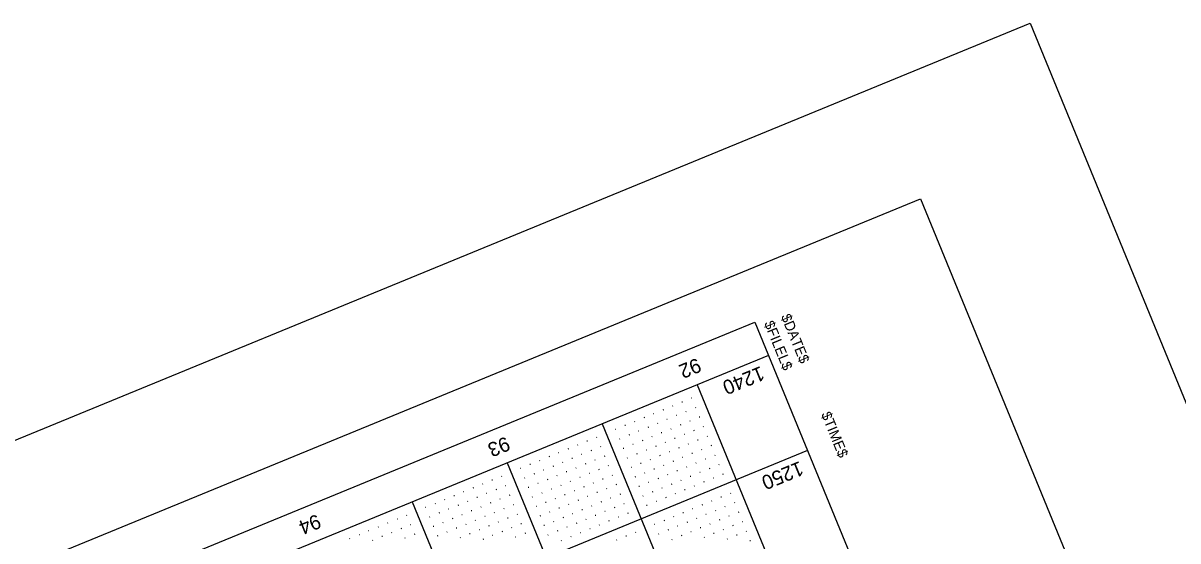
# Model space of a CAD drawing. Extents: x 2148770 to 2150891, y 142633 to 144465.
# Drawn here: x 2149944 to 2150507, y 144175 to 144427 of the extents above; entities that cross this region are included whole.
import ezdxf

# ---------------------------------------------------------------- set-up
doc = ezdxf.new("R2010")
doc.units = 0
for name, color, linetype in [('SHT_Plan_Profile_Sheet_Elev_Txt', 7, 'Continuous'), ('SHT_Plan_Profile_Sheet_Sta_Txt', 7, 'Continuous'), ('SHT_Plot_Shape_Full', 7, 'Continuous'), ('SHT_Plot_Shape_Half', 7, 'Continuous'), ('SHT_Plot_Stamp', 7, 'Continuous'), ('SHT_Profile_Grid_Major', 7, 'Continuous'), ('SHT_Profile_Grid_Minor', 7, 'Continuous'), ('SHT_Sheet_Border', 7, 'Continuous')]:
    doc.layers.add(name, color=color, linetype=linetype)

msp = doc.modelspace()

# ---------------------------------------------------------------- linework, layer by layer
at = {"layer": 'SHT_Plot_Shape_Full'}
msp.add_lwpolyline([(2150890.55, 143316.95), (2149225.42, 142633.31), (2148769.66, 143743.39), (2150434.78, 144427.04)], close=True, dxfattribs=at)
at = {"layer": 'SHT_Plot_Shape_Half'}
msp.add_lwpolyline([(2150799.14, 143324.02), (2149226.52, 142678.36), (2148808.74, 143695.93), (2150381.36, 144341.59)], close=True, dxfattribs=at)
at = {"layer": 'SHT_Profile_Grid_Major'}
for p, q in [((2150226.36, 144232.01), (2150416.26, 143769.48)), ((2150326.3, 144218.99), (2148869.31, 143620.81)), ((2150180.11, 144213.02), (2150370.01, 143750.49)), ((2150133.85, 144194.03), (2150323.76, 143731.5))]:
    msp.add_line(p, q, dxfattribs=at)
at = {"layer": 'SHT_Profile_Grid_Minor'}
for p, q in [((2150265.38, 144242.63), (2150265.15, 144242.53)), ((2150270, 144244.53), (2150269.77, 144244.43)), ((2150251.5, 144236.93), (2150251.27, 144236.83)), ((2150256.13, 144238.83), (2150255.9, 144238.73)), ((2150260.75, 144240.73), (2150260.52, 144240.63)), ((2150267.28, 144238), (2150267.05, 144237.91)), ((2150271.9, 144239.9), (2150271.67, 144239.81)), ((2150237.63, 144231.23), (2150237.4, 144231.14)), ((2150242.25, 144233.13), (2150242.02, 144233.04)), ((2150246.88, 144235.03), (2150246.65, 144234.94)), ((2150253.4, 144232.3), (2150253.17, 144232.21)), ((2150258.03, 144234.2), (2150257.8, 144234.11)), ((2150262.65, 144236.1), (2150262.42, 144236.01)), ((2150264.55, 144231.48), (2150264.32, 144231.38)), ((2150269.18, 144233.38), (2150268.95, 144233.28)), ((2150273.8, 144235.28), (2150273.57, 144235.18)), ((2150223.75, 144225.54), (2150223.52, 144225.44)), ((2150233, 144229.33), (2150232.77, 144229.24)), ((2150239.53, 144226.61), (2150239.29, 144226.51)), ((2150244.15, 144228.51), (2150243.92, 144228.41)), ((2150248.78, 144230.41), (2150248.55, 144230.31)), ((2150250.68, 144225.78), (2150250.44, 144225.69)), ((2150255.3, 144227.68), (2150255.07, 144227.58)), ((2150259.93, 144229.58), (2150259.7, 144229.48)), ((2150266.45, 144226.85), (2150266.22, 144226.76)), ((2150271.08, 144228.75), (2150270.84, 144228.66)), ((2150275.7, 144230.65), (2150275.47, 144230.55)), ((2150277.6, 144226.02), (2150277.37, 144225.93)), ((2150209.88, 144219.84), (2150209.64, 144219.74)), ((2150214.5, 144221.74), (2150214.27, 144221.64)), ((2150219.13, 144223.64), (2150218.89, 144223.54)), ((2150225.65, 144220.91), (2150225.42, 144220.82)), ((2150234.9, 144224.71), (2150234.67, 144224.61)), ((2150236.8, 144220.08), (2150236.57, 144219.99)), ((2150241.43, 144221.98), (2150241.19, 144221.89)), ((2150246.05, 144223.88), (2150245.82, 144223.79)), ((2150252.57, 144221.15), (2150252.34, 144221.06)), ((2150257.2, 144223.05), (2150256.97, 144222.96)), ((2150261.83, 144224.95), (2150261.59, 144224.86)), ((2150263.72, 144220.33), (2150263.49, 144220.23)), ((2150268.35, 144222.23), (2150268.12, 144222.13)), ((2150272.98, 144224.13), (2150272.74, 144224.03)), ((2150274.87, 144219.5), (2150274.64, 144219.41)), ((2150279.5, 144221.4), (2150279.27, 144221.3)), ((2150196, 144214.14), (2150195.77, 144214.05)), ((2150200.62, 144216.04), (2150200.39, 144215.95)), ((2150205.25, 144217.94), (2150205.02, 144217.84)), ((2150211.77, 144215.21), (2150211.54, 144215.12)), ((2150216.4, 144217.11), (2150216.17, 144217.02)), ((2150221.02, 144219.01), (2150220.79, 144218.92)), ((2150222.92, 144214.39), (2150222.69, 144214.29)), ((2150227.55, 144216.29), (2150227.32, 144216.19)), ((2150238.7, 144215.46), (2150238.47, 144215.36)), ((2150243.32, 144217.36), (2150243.09, 144217.26)), ((2150247.95, 144219.26), (2150247.72, 144219.16)), ((2150249.85, 144214.63), (2150249.62, 144214.54)), ((2150254.47, 144216.53), (2150254.24, 144216.43)), ((2150259.1, 144218.43), (2150258.87, 144218.33)), ((2150265.62, 144215.7), (2150265.39, 144215.61)), ((2150270.25, 144217.6), (2150270.02, 144217.51)), ((2150276.77, 144214.87), (2150276.54, 144214.78)), ((2150281.4, 144216.77), (2150281.17, 144216.68)), ((2150186.75, 144210.34), (2150186.52, 144210.25)), ((2150191.37, 144212.24), (2150191.14, 144212.15)), ((2150197.9, 144209.52), (2150197.67, 144209.42)), ((2150202.52, 144211.42), (2150202.29, 144211.32)), ((2150207.15, 144213.31), (2150206.92, 144213.22)), ((2150209.05, 144208.69), (2150208.82, 144208.59)), ((2150213.67, 144210.59), (2150213.44, 144210.49)), ((2150218.3, 144212.49), (2150218.07, 144212.39)), ((2150224.82, 144209.76), (2150224.59, 144209.67)), ((2150229.45, 144211.66), (2150229.22, 144211.56)), ((2150240.6, 144210.83), (2150240.37, 144210.74)), ((2150245.22, 144212.73), (2150244.99, 144212.64)), ((2150251.75, 144210.01), (2150251.52, 144209.91)), ((2150256.37, 144211.9), (2150256.14, 144211.81)), ((2150261, 144213.8), (2150260.77, 144213.71)), ((2150262.9, 144209.18), (2150262.67, 144209.08)), ((2150267.52, 144211.08), (2150267.29, 144210.98)), ((2150272.15, 144212.98), (2150271.92, 144212.88)), ((2150274.05, 144208.35), (2150273.82, 144208.26)), ((2150278.67, 144210.25), (2150278.44, 144210.15)), ((2150283.3, 144212.15), (2150283.07, 144212.05)), ((2150168.25, 144202.75), (2150168.02, 144202.65)), ((2150172.87, 144204.65), (2150172.64, 144204.55)), ((2150177.5, 144206.55), (2150177.27, 144206.45)), ((2150188.65, 144205.72), (2150188.42, 144205.62)), ((2150193.27, 144207.62), (2150193.04, 144207.52)), ((2150195.17, 144202.99), (2150194.94, 144202.9)), ((2150199.8, 144204.89), (2150199.57, 144204.8)), ((2150204.42, 144206.79), (2150204.19, 144206.7)), ((2150210.95, 144204.06), (2150210.72, 144203.97)), ((2150215.57, 144205.96), (2150215.34, 144205.87)), ((2150220.2, 144207.86), (2150219.97, 144207.77)), ((2150222.1, 144203.24), (2150221.87, 144203.14)), ((2150226.72, 144205.14), (2150226.49, 144205.04)), ((2150231.35, 144207.03), (2150231.12, 144206.94)), ((2150242.5, 144206.21), (2150242.27, 144206.11)), ((2150247.12, 144208.11), (2150246.89, 144208.01)), ((2150249.02, 144203.48), (2150248.79, 144203.39)), ((2150253.65, 144205.38), (2150253.42, 144205.28)), ((2150258.27, 144207.28), (2150258.04, 144207.18)), ((2150260.17, 144202.65), (2150259.94, 144202.56)), ((2150264.8, 144204.55), (2150264.56, 144204.46)), ((2150269.42, 144206.45), (2150269.19, 144206.36)), ((2150275.95, 144203.73), (2150275.71, 144203.63)), ((2150280.57, 144205.62), (2150280.34, 144205.53)), ((2150285.2, 144207.52), (2150284.97, 144207.43)), ((2150154.37, 144197.05), (2150154.14, 144196.96)), ((2150159, 144198.95), (2150158.76, 144198.85)), ((2150163.62, 144200.85), (2150163.39, 144200.75)), ((2150170.15, 144198.12), (2150169.91, 144198.03)), ((2150174.77, 144200.02), (2150174.54, 144199.93)), ((2150179.4, 144201.92), (2150179.17, 144201.83)), ((2150181.3, 144197.3), (2150181.06, 144197.2)), ((2150190.55, 144201.09), (2150190.32, 144201)), ((2150197.07, 144198.37), (2150196.84, 144198.27)), ((2150201.7, 144200.27), (2150201.46, 144200.17)), ((2150206.32, 144202.16), (2150206.09, 144202.07)), ((2150208.22, 144197.54), (2150207.99, 144197.44)), ((2150212.85, 144199.44), (2150212.61, 144199.34)), ((2150217.47, 144201.34), (2150217.24, 144201.24)), ((2150224, 144198.61), (2150223.76, 144198.52)), ((2150228.62, 144200.51), (2150228.39, 144200.42)), ((2150233.25, 144202.41), (2150233.01, 144202.31)), ((2150235.15, 144197.78), (2150234.91, 144197.69)), ((2150244.4, 144201.58), (2150244.16, 144201.49)), ((2150246.29, 144196.96), (2150246.06, 144196.86)), ((2150250.92, 144198.86), (2150250.69, 144198.76)), ((2150255.55, 144200.75), (2150255.31, 144200.66)), ((2150262.07, 144198.03), (2150261.84, 144197.93)), ((2150266.7, 144199.93), (2150266.46, 144199.83)), ((2150271.32, 144201.83), (2150271.09, 144201.73)), ((2150288.99, 144198.27), (2150288.76, 144198.18)), ((2150140.49, 144191.35), (2150140.26, 144191.26)), ((2150145.12, 144193.25), (2150144.89, 144193.16)), ((2150149.75, 144195.15), (2150149.51, 144195.06)), ((2150156.27, 144192.43), (2150156.04, 144192.33)), ((2150160.9, 144194.32), (2150160.66, 144194.23)), ((2150165.52, 144196.22), (2150165.29, 144196.13)), ((2150167.42, 144191.6), (2150167.19, 144191.5)), ((2150172.04, 144193.5), (2150171.81, 144193.4)), ((2150176.67, 144195.4), (2150176.44, 144195.3)), ((2150183.19, 144192.67), (2150182.96, 144192.57)), ((2150192.45, 144196.47), (2150192.21, 144196.37)), ((2150194.34, 144191.84), (2150194.11, 144191.75)), ((2150198.97, 144193.74), (2150198.74, 144193.65)), ((2150203.6, 144195.64), (2150203.36, 144195.55)), ((2150210.12, 144192.91), (2150209.89, 144192.82)), ((2150214.74, 144194.81), (2150214.51, 144194.72)), ((2150219.37, 144196.71), (2150219.14, 144196.62)), ((2150221.27, 144192.09), (2150221.04, 144191.99)), ((2150225.89, 144193.99), (2150225.66, 144193.89)), ((2150230.52, 144195.88), (2150230.29, 144195.79)), ((2150237.04, 144193.16), (2150236.81, 144193.06)), ((2150248.19, 144192.33), (2150247.96, 144192.24)), ((2150252.82, 144194.23), (2150252.59, 144194.14)), ((2150257.44, 144196.13), (2150257.21, 144196.03)), ((2150275.12, 144192.58), (2150274.89, 144192.48)), ((2150279.74, 144194.47), (2150279.51, 144194.38)), ((2150284.37, 144196.37), (2150284.14, 144196.28)), ((2150286.27, 144191.75), (2150286.04, 144191.65)), ((2150290.89, 144193.65), (2150290.66, 144193.55)), ((2150131.24, 144187.56), (2150131.01, 144187.46)), ((2150142.39, 144186.73), (2150142.16, 144186.63)), ((2150147.02, 144188.63), (2150146.79, 144188.53)), ((2150151.64, 144190.53), (2150151.41, 144190.43)), ((2150153.54, 144185.9), (2150153.31, 144185.81)), ((2150158.17, 144187.8), (2150157.94, 144187.71)), ((2150162.79, 144189.7), (2150162.56, 144189.6)), ((2150169.32, 144186.97), (2150169.09, 144186.88)), ((2150173.94, 144188.87), (2150173.71, 144188.78)), ((2150178.57, 144190.77), (2150178.34, 144190.68)), ((2150180.47, 144186.15), (2150180.24, 144186.05)), ((2150185.09, 144188.04), (2150184.86, 144187.95)), ((2150196.24, 144187.22), (2150196.01, 144187.12)), ((2150200.87, 144189.12), (2150200.64, 144189.02)), ((2150205.49, 144191.02), (2150205.26, 144190.92)), ((2150207.39, 144186.39), (2150207.16, 144186.29)), ((2150212.02, 144188.29), (2150211.79, 144188.19)), ((2150216.64, 144190.19), (2150216.41, 144190.09)), ((2150223.17, 144187.46), (2150222.94, 144187.37)), ((2150227.79, 144189.36), (2150227.56, 144189.27)), ((2150232.42, 144191.26), (2150232.19, 144191.16)), ((2150234.32, 144186.63), (2150234.09, 144186.54)), ((2150238.94, 144188.53), (2150238.71, 144188.44)), ((2150261.24, 144186.88), (2150261.01, 144186.78)), ((2150265.87, 144188.78), (2150265.64, 144188.68)), ((2150270.49, 144190.68), (2150270.26, 144190.58)), ((2150272.39, 144186.05), (2150272.16, 144185.96)), ((2150277.02, 144187.95), (2150276.79, 144187.86)), ((2150281.64, 144189.85), (2150281.41, 144189.75)), ((2150288.17, 144187.12), (2150287.94, 144187.03)), ((2150292.79, 144189.02), (2150292.56, 144188.93)), ((2150117.37, 144181.86), (2150117.14, 144181.76)), ((2150121.99, 144183.76), (2150121.76, 144183.66)), ((2150126.62, 144185.66), (2150126.39, 144185.56)), ((2150128.52, 144181.03), (2150128.29, 144180.94)), ((2150133.14, 144182.93), (2150132.91, 144182.84)), ((2150144.29, 144182.1), (2150144.06, 144182.01)), ((2150148.92, 144184), (2150148.69, 144183.91)), ((2150155.44, 144181.28), (2150155.21, 144181.18)), ((2150160.07, 144183.17), (2150159.84, 144183.08)), ((2150164.69, 144185.07), (2150164.46, 144184.98)), ((2150166.59, 144180.45), (2150166.36, 144180.35)), ((2150171.22, 144182.35), (2150170.99, 144182.25)), ((2150175.84, 144184.25), (2150175.61, 144184.15)), ((2150182.37, 144181.52), (2150182.14, 144181.43)), ((2150186.99, 144183.42), (2150186.76, 144183.32)), ((2150198.14, 144182.59), (2150197.91, 144182.5)), ((2150202.77, 144184.49), (2150202.54, 144184.4)), ((2150209.29, 144181.76), (2150209.06, 144181.67)), ((2150213.92, 144183.66), (2150213.69, 144183.57)), ((2150218.54, 144185.56), (2150218.31, 144185.47)), ((2150220.44, 144180.94), (2150220.21, 144180.84)), ((2150225.07, 144182.84), (2150224.84, 144182.74)), ((2150229.69, 144184.74), (2150229.46, 144184.64)), ((2150251.99, 144183.08), (2150251.76, 144182.99)), ((2150256.62, 144184.98), (2150256.39, 144184.88)), ((2150258.52, 144180.35), (2150258.28, 144180.26)), ((2150263.14, 144182.25), (2150262.91, 144182.16)), ((2150267.77, 144184.15), (2150267.54, 144184.06)), ((2150274.29, 144181.43), (2150274.06, 144181.33)), ((2150278.92, 144183.32), (2150278.69, 144183.23)), ((2150283.54, 144185.22), (2150283.31, 144185.13)), ((2150285.44, 144180.6), (2150285.21, 144180.5)), ((2150290.07, 144182.5), (2150289.83, 144182.4)), ((2150294.69, 144184.4), (2150294.46, 144184.3)), ((2150103.49, 144176.16), (2150103.26, 144176.07)), ((2150108.12, 144178.06), (2150107.89, 144177.97)), ((2150112.74, 144179.96), (2150112.51, 144179.86)), ((2150114.64, 144175.33), (2150114.41, 144175.24)), ((2150119.27, 144177.23), (2150119.04, 144177.14)), ((2150123.89, 144179.13), (2150123.66, 144179.04)), ((2150130.42, 144176.41), (2150130.19, 144176.31)), ((2150135.04, 144178.31), (2150134.81, 144178.21)), ((2150146.19, 144177.48), (2150145.96, 144177.38)), ((2150150.82, 144179.38), (2150150.59, 144179.28)), ((2150157.34, 144176.65), (2150157.11, 144176.56)), ((2150161.97, 144178.55), (2150161.74, 144178.45)), ((2150168.49, 144175.82), (2150168.26, 144175.73)), ((2150173.12, 144177.72), (2150172.89, 144177.63)), ((2150177.74, 144179.62), (2150177.51, 144179.53)), ((2150184.27, 144176.89), (2150184.03, 144176.8)), ((2150188.89, 144178.79), (2150188.66, 144178.7)), ((2150200.04, 144177.97), (2150199.81, 144177.87)), ((2150204.67, 144179.87), (2150204.44, 144179.77)), ((2150206.57, 144175.24), (2150206.33, 144175.15)), ((2150211.19, 144177.14), (2150210.96, 144177.04)), ((2150215.82, 144179.04), (2150215.59, 144178.94)), ((2150233.49, 144175.48), (2150233.26, 144175.39)), ((2150238.12, 144177.38), (2150237.88, 144177.29)), ((2150242.74, 144179.28), (2150242.51, 144179.19)), ((2150253.89, 144178.46), (2150253.66, 144178.36)), ((2150260.42, 144175.73), (2150260.18, 144175.63)), ((2150265.04, 144177.63), (2150264.81, 144177.53)), ((2150269.67, 144179.53), (2150269.43, 144179.43)), ((2150276.19, 144176.8), (2150275.96, 144176.71)), ((2150280.82, 144178.7), (2150280.58, 144178.6)), ((2150287.34, 144175.97), (2150287.11, 144175.88)), ((2150291.97, 144177.87), (2150291.73, 144177.78)), ((2150296.59, 144179.77), (2150296.36, 144179.68)), ((2150298.49, 144175.15), (2150298.26, 144175.05))]:
    msp.add_line(p, q, dxfattribs=at)
at = {"layer": 'SHT_Sheet_Border'}
for p, q in [((2150307.31, 144265.25), (2149093.15, 143766.76)), ((2150272.62, 144251), (2150462.52, 143788.47))]:
    msp.add_line(p, q, dxfattribs=at)
msp.add_lwpolyline([(2150699.45, 143310.11), (2149242.47, 142711.93), (2148843.68, 143683.25), (2150300.66, 144281.43)], close=True, dxfattribs=at)

# ---------------------------------------------------------------- texts
at = {"layer": 'SHT_Plan_Profile_Sheet_Elev_Txt'}
for s, p in [('1240', (2150303.51, 144260.28)), ('1250', (2150322.5, 144214.02))]:
    msp.add_text(s, height=7, rotation=202.3213, dxfattribs=at).set_placement(p)
at = {"layer": 'SHT_Plan_Profile_Sheet_Sta_Txt'}
for s, p in [('92', (2150272.63, 144264.25)), ('93', (2150179.55, 144226.03)), ('94', (2150087.49, 144188.24))]:
    msp.add_text(s, height=7, rotation=202.3213, dxfattribs=at).set_placement(p)
at = {"layer": 'SHT_Plot_Stamp'}
for s, p in [('$FILEL$', (2150305.04, 144280.94)), ('$DATE$', (2150313.25, 144284.31)), ('$TIME$', (2150332.81, 144236.68))]:
    msp.add_text(s, height=5, rotation=292.3213, dxfattribs=at).set_placement(p)

doc.saveas('drawing.dxf')
